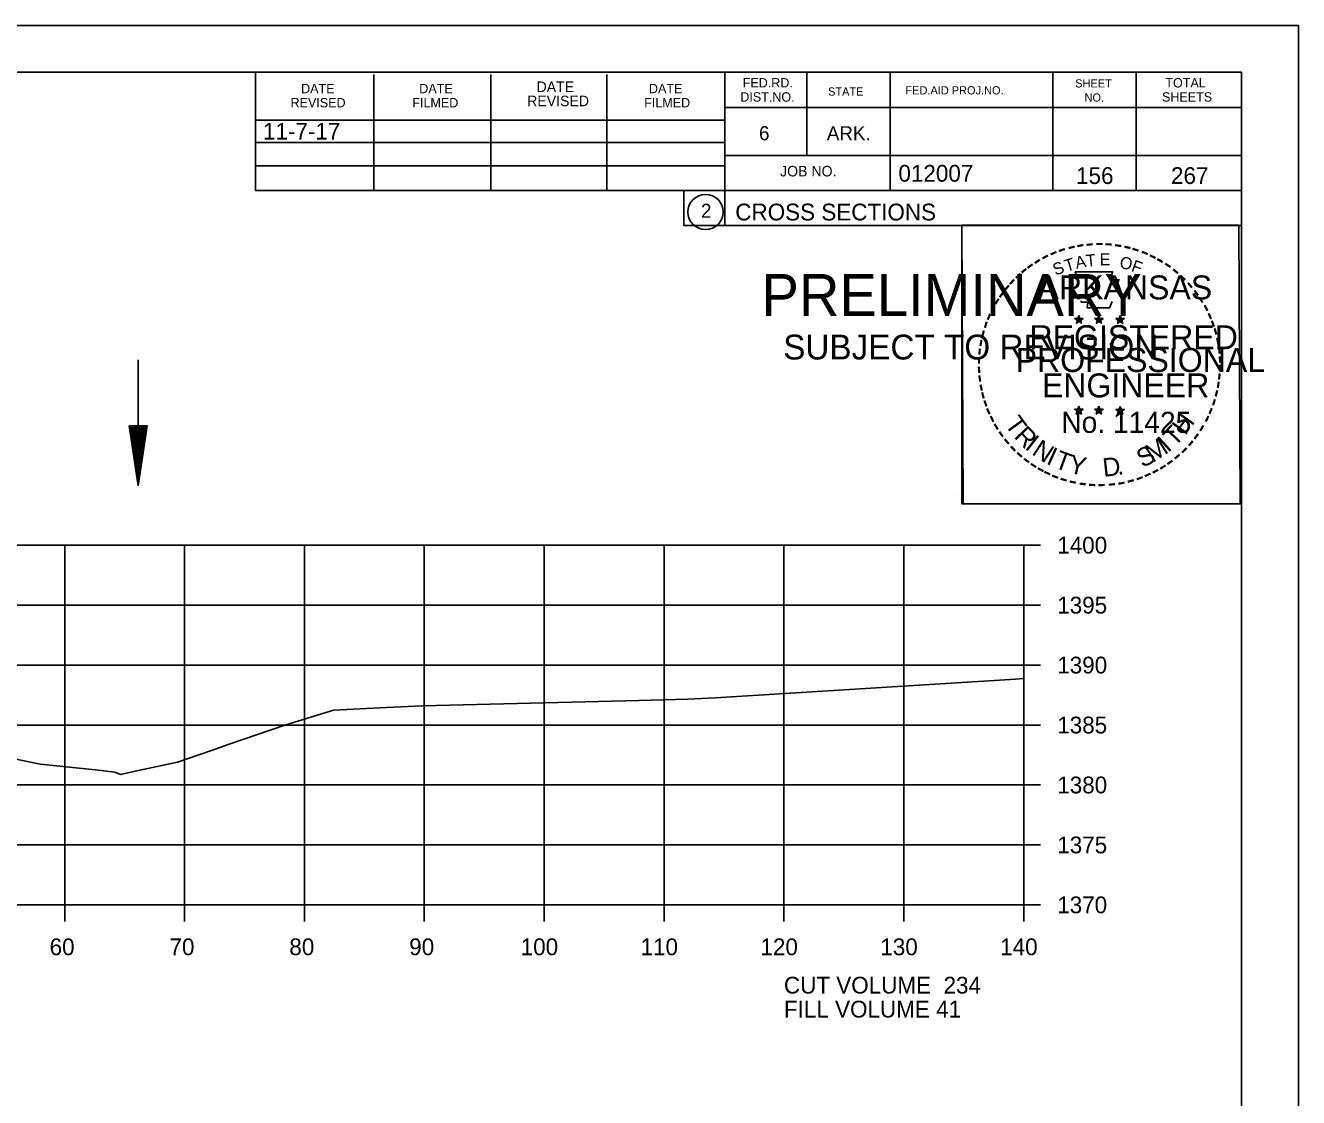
# Model space of a CAD drawing. Extents: x 1374311 to 1383814, y 384102 to 406278.
# Drawn here: x 1381685.4 to 1381791.6, y 385941.9 to 386031.3 of the extents above; entities that cross this region are included whole.
import ezdxf

# ---------------------------------------------------------------- set-up
doc = ezdxf.new("R2010")
doc.units = 0
for name, color, linetype in [('R_Axis', 7, 'Continuous'), ('R_Axis Annot', 7, 'Continuous'), ('R_Border', 7, 'Continuous'), ('R_Border PE', 7, 'Continuous'), ('R_Border Prem', 7, 'Continuous'), ('R_Draft', 7, 'Continuous'), ('R_Exist Surface', 7, 'Continuous'), ('R_Fin Surface', 7, 'Continuous'), ('R_Grid', 7, 'Continuous'), ('R_No Plot', 7, 'Continuous'), ('R_Water', 7, 'Continuous')]:
    doc.layers.add(name, color=color, linetype=linetype)

msp = doc.modelspace()

# ---------------------------------------------------------------- linework, layer by layer
at = {"layer": 'R_Axis'}
for p, q in [((1381768.66, 385957.95), (1381768.66, 385987.95)), ((1381770.06, 385987.95), (1381768.66, 385987.95)), ((1381770.06, 385982.95), (1381768.66, 385982.95)), ((1381770.06, 385977.95), (1381768.66, 385977.95)), ((1381770.06, 385972.95), (1381768.66, 385972.95)), ((1381770.06, 385967.95), (1381768.66, 385967.95)), ((1381770.06, 385962.95), (1381768.66, 385962.95)), ((1381488.66, 385957.95), (1381768.66, 385957.95)), ((1381688.66, 385956.55), (1381688.66, 385957.95)), ((1381698.66, 385956.55), (1381698.66, 385957.95)), ((1381708.66, 385956.55), (1381708.66, 385957.95)), ((1381718.66, 385956.55), (1381718.66, 385957.95)), ((1381728.66, 385956.55), (1381728.66, 385957.95)), ((1381738.66, 385956.55), (1381738.66, 385957.95)), ((1381748.66, 385956.55), (1381748.66, 385957.95)), ((1381758.66, 385956.55), (1381758.66, 385957.95)), ((1381768.66, 385956.55), (1381768.66, 385957.95)), ((1381770.06, 385957.95), (1381768.66, 385957.95))]:
    msp.add_line(p, q, dxfattribs=at)
at = {"layer": 'R_Border'}
for p, q in [((1381470.66, 386027.41), (1381786.84, 386027.41)), ((1381704.58, 386017.53), (1381704.58, 386027.41)), ((1381714.44, 386017.53), (1381714.44, 386027.21)), ((1381724.2, 386017.53), (1381724.2, 386027.21)), ((1381733.88, 386017.53), (1381733.88, 386027.21)), ((1381743.74, 386027.41), (1381743.74, 386014.61)), ((1381750.58, 386027.41), (1381750.58, 386020.47)), ((1381757.52, 386027.41), (1381757.52, 386017.53)), ((1381771.1, 386027.41), (1381771.1, 386017.53)), ((1381778.04, 386027.41), (1381778.04, 386017.53)), ((1381786.84, 385821.95), (1381786.84, 386027.41)), ((1381786.84, 386024.47), (1381743.74, 386024.47)), ((1381786.84, 386024.49), (1381786.84, 386024.49)), ((1381704.58, 386023.39), (1381743.74, 386023.39)), ((1381704.58, 386021.53), (1381743.74, 386021.53)), ((1381786.84, 386020.47), (1381743.74, 386020.47)), ((1381746.7, 386020.47), (1381786.84, 386020.47)), ((1381704.58, 386017.53), (1381704.58, 386019.59)), ((1381704.58, 386019.59), (1381743.74, 386019.59)), ((1381786.84, 386017.53), (1381704.58, 386017.53)), ((1381743.74, 386014.61), (1381786.84, 386014.61))]:
    msp.add_line(p, q, dxfattribs=at)
msp.add_circle((1381742.12, 386015.74), 1.47, dxfattribs=at)
at = {"layer": 'R_Border PE'}
for p, q in [((1381772.92, 386006.86), (1381773.27, 386006.75)), ((1381772.92, 386006.86), (1381773.18, 386006.82)), ((1381772.92, 386006.86), (1381773.16, 386006.74)), ((1381773.06, 386006.46), (1381773.27, 386006.75)), ((1381773.06, 386006.46), (1381773.18, 386006.7)), ((1381773.06, 386006.46), (1381773.27, 386006.67)), ((1381773.27, 386007.12), (1381773.23, 386006.87)), ((1381773.27, 386006.75), (1381773.27, 386007.12)), ((1381773.27, 386007.12), (1381773.32, 386006.87)), ((1381773.62, 386006.86), (1381773.27, 386006.75)), ((1381773.48, 386006.46), (1381773.27, 386006.75)), ((1381773.48, 386006.46), (1381773.27, 386006.67)), ((1381773.62, 386006.86), (1381773.33, 386006.81)), ((1381773.48, 386006.46), (1381773.35, 386006.75)), ((1381773.62, 386006.86), (1381773.41, 386006.76)), ((1381774.59, 386006.86), (1381774.94, 386006.75)), ((1381774.59, 386006.86), (1381774.85, 386006.82)), ((1381774.59, 386006.86), (1381774.83, 386006.74)), ((1381774.73, 386006.46), (1381774.94, 386006.75)), ((1381774.73, 386006.46), (1381774.85, 386006.7)), ((1381774.73, 386006.46), (1381774.94, 386006.67)), ((1381774.94, 386007.12), (1381774.9, 386006.87)), ((1381774.94, 386006.75), (1381774.94, 386007.12)), ((1381774.94, 386007.12), (1381774.99, 386006.87)), ((1381775.29, 386006.86), (1381774.94, 386006.75)), ((1381775.15, 386006.46), (1381774.94, 386006.75)), ((1381775.15, 386006.46), (1381774.94, 386006.67)), ((1381775.29, 386006.86), (1381775, 386006.81)), ((1381775.15, 386006.46), (1381775.02, 386006.75)), ((1381775.29, 386006.86), (1381775.08, 386006.76)), ((1381776.36, 386006.85), (1381776.71, 386006.74)), ((1381776.36, 386006.85), (1381776.61, 386006.81)), ((1381776.36, 386006.85), (1381776.59, 386006.73)), ((1381776.49, 386006.44), (1381776.71, 386006.74)), ((1381776.49, 386006.44), (1381776.62, 386006.69)), ((1381776.49, 386006.44), (1381776.7, 386006.66)), ((1381776.71, 386007.11), (1381776.66, 386006.85)), ((1381776.92, 386006.44), (1381776.7, 386006.66)), ((1381776.71, 386006.74), (1381776.71, 386007.11)), ((1381776.71, 386007.11), (1381776.75, 386006.86)), ((1381777.05, 386006.85), (1381776.71, 386006.74)), ((1381776.92, 386006.44), (1381776.71, 386006.74)), ((1381777.05, 386006.85), (1381776.77, 386006.8)), ((1381776.92, 386006.44), (1381776.78, 386006.73)), ((1381777.05, 386006.85), (1381776.85, 386006.75)), ((1381772.92, 385999.29), (1381773.27, 385999.18)), ((1381772.92, 385999.29), (1381773.17, 385999.25)), ((1381772.92, 385999.29), (1381773.16, 385999.17)), ((1381773.05, 385998.88), (1381773.27, 385999.18)), ((1381773.05, 385998.88), (1381773.18, 385999.13)), ((1381773.05, 385998.88), (1381773.27, 385999.1)), ((1381773.27, 385999.54), (1381773.23, 385999.29)), ((1381773.27, 385999.18), (1381773.27, 385999.54)), ((1381773.27, 385999.54), (1381773.32, 385999.29)), ((1381773.61, 385999.29), (1381773.27, 385999.18)), ((1381773.48, 385998.88), (1381773.27, 385999.18)), ((1381773.48, 385998.88), (1381773.27, 385999.1)), ((1381773.61, 385999.29), (1381773.33, 385999.24)), ((1381773.48, 385998.88), (1381773.34, 385999.17)), ((1381773.61, 385999.29), (1381773.41, 385999.19)), ((1381774.59, 385999.29), (1381774.94, 385999.18)), ((1381774.59, 385999.29), (1381774.84, 385999.25)), ((1381774.59, 385999.29), (1381774.82, 385999.17)), ((1381774.72, 385998.88), (1381774.94, 385999.18)), ((1381774.72, 385998.88), (1381774.85, 385999.13)), ((1381774.72, 385998.88), (1381774.93, 385999.1)), ((1381774.94, 385999.54), (1381774.9, 385999.29)), ((1381775.15, 385998.88), (1381774.93, 385999.1)), ((1381774.94, 385999.18), (1381774.94, 385999.54)), ((1381774.94, 385999.54), (1381774.99, 385999.29)), ((1381775.28, 385999.29), (1381774.94, 385999.18)), ((1381775.15, 385998.88), (1381774.94, 385999.18)), ((1381775.28, 385999.29), (1381775, 385999.24)), ((1381775.15, 385998.88), (1381775.01, 385999.17)), ((1381775.28, 385999.29), (1381775.08, 385999.19)), ((1381776.35, 385999.28), (1381776.7, 385999.17)), ((1381776.35, 385999.28), (1381776.61, 385999.24)), ((1381776.35, 385999.28), (1381776.59, 385999.16)), ((1381776.49, 385998.87), (1381776.7, 385999.17)), ((1381776.49, 385998.87), (1381776.61, 385999.12)), ((1381776.49, 385998.87), (1381776.7, 385999.09)), ((1381776.7, 385999.53), (1381776.66, 385999.28)), ((1381776.7, 385999.17), (1381776.7, 385999.53)), ((1381776.7, 385999.53), (1381776.75, 385999.28)), ((1381777.05, 385999.28), (1381776.7, 385999.17)), ((1381776.92, 385998.87), (1381776.7, 385999.17)), ((1381776.92, 385998.87), (1381776.7, 385999.09)), ((1381777.05, 385999.28), (1381776.76, 385999.23)), ((1381776.92, 385998.87), (1381776.78, 385999.16)), ((1381777.05, 385999.28), (1381776.85, 385999.18))]:
    msp.add_line(p, q, dxfattribs=at)
for points in [[(1381772.96, 386010.74), (1381773.23, 386009.91)], [(1381776.47, 386009.82), (1381776.62, 386010.1), (1381775.93, 386010.08), (1381776.08, 386010.74), (1381772.96, 386010.74)], [(1381773.46, 386008.32), (1381773.46, 386008.23), (1381774.02, 386008.21), (1381773.96, 386007.74), (1381775.83, 386007.74), (1381776.04, 386008.28)], [(1381773.27, 386007.12), (1381773.48, 386006.46), (1381772.92, 386006.86), (1381773.62, 386006.86), (1381773.06, 386006.46), (1381773.27, 386007.12)], [(1381774.94, 386007.12), (1381775.15, 386006.46), (1381774.59, 386006.86), (1381775.29, 386006.86), (1381774.73, 386006.46), (1381774.94, 386007.12)], [(1381776.71, 386007.11), (1381776.92, 386006.44), (1381776.36, 386006.85), (1381777.05, 386006.85), (1381776.49, 386006.44), (1381776.71, 386007.11)], [(1381773.27, 385999.54), (1381773.48, 385998.88), (1381772.92, 385999.29), (1381773.61, 385999.29), (1381773.05, 385998.88), (1381773.27, 385999.54)], [(1381774.94, 385999.54), (1381775.15, 385998.88), (1381774.59, 385999.29), (1381775.28, 385999.29), (1381774.72, 385998.88), (1381774.94, 385999.54)], [(1381776.7, 385999.53), (1381776.92, 385998.87), (1381776.35, 385999.28), (1381777.05, 385999.28), (1381776.49, 385998.87), (1381776.7, 385999.53)]]:
    msp.add_lwpolyline(points, dxfattribs=at)
for centre, radius in [((1381773.27, 386006.75), 0.172), ((1381773.27, 386006.75), 0.145), ((1381773.27, 386006.75), 0.116), ((1381773.27, 386006.75), 0.0991), ((1381773.27, 386006.75), 0.0747), ((1381773.27, 386006.75), 0.0495), ((1381773.27, 386006.75), 0.0296), ((1381774.94, 386006.75), 0.172), ((1381774.94, 386006.75), 0.145), ((1381774.94, 386006.75), 0.116), ((1381774.94, 386006.75), 0.0991), ((1381774.94, 386006.75), 0.0747), ((1381774.94, 386006.75), 0.0495), ((1381774.94, 386006.75), 0.0296), ((1381776.7, 386006.74), 0.172), ((1381776.7, 386006.74), 0.145), ((1381776.7, 386006.74), 0.116), ((1381776.7, 386006.74), 0.0991), ((1381776.7, 386006.74), 0.0747), ((1381776.7, 386006.74), 0.0495), ((1381776.7, 386006.74), 0.0296), ((1381773.27, 385999.18), 0.172), ((1381773.27, 385999.18), 0.145), ((1381773.27, 385999.18), 0.116), ((1381773.27, 385999.18), 0.0991), ((1381773.27, 385999.18), 0.0747), ((1381773.27, 385999.18), 0.0495), ((1381773.27, 385999.18), 0.0296), ((1381774.94, 385999.18), 0.172), ((1381774.94, 385999.18), 0.145), ((1381774.94, 385999.18), 0.116), ((1381774.94, 385999.18), 0.0991), ((1381774.94, 385999.18), 0.0747), ((1381774.94, 385999.18), 0.0495), ((1381774.94, 385999.18), 0.0296), ((1381776.7, 385999.17), 0.172), ((1381776.7, 385999.17), 0.145), ((1381776.7, 385999.17), 0.116), ((1381776.7, 385999.17), 0.0991), ((1381776.7, 385999.17), 0.0747), ((1381776.7, 385999.17), 0.0495), ((1381776.7, 385999.17), 0.0296)]:
    msp.add_circle(centre, radius, dxfattribs=at)
at = {"layer": 'R_Draft'}
for p, q in [((1381694.03, 385997.9), (1381694.78, 385992.9)), ((1381695.53, 385997.9), (1381694.03, 385997.9)), ((1381694.15, 385997.9), (1381694.78, 385993.74)), ((1381694.28, 385997.9), (1381694.78, 385994.6)), ((1381694.41, 385997.9), (1381694.78, 385995.43)), ((1381694.53, 385997.9), (1381694.78, 385996.28)), ((1381694.66, 385997.9), (1381694.78, 385997.11)), ((1381695.53, 385997.9), (1381694.78, 385992.9)), ((1381695.02, 385997.9), (1381694.78, 385996.28)), ((1381695.28, 385997.9), (1381694.78, 385994.6)), ((1381695.4, 385997.9), (1381694.78, 385993.74)), ((1381695.15, 385997.9), (1381694.78, 385995.43)), ((1381694.9, 385997.9), (1381694.78, 385997.11))]:
    msp.add_line(p, q, dxfattribs=at)
at = {"layer": 'R_Exist Surface'}
msp.add_lwpolyline([(1381684.47, 385970.14), (1381686.6, 385969.69), (1381691.22, 385969.22), (1381692.83, 385969.02), (1381693.31, 385968.83), (1381694.68, 385969.13), (1381698.08, 385969.85), (1381700.91, 385970.82), (1381702.37, 385971.34), (1381707.02, 385972.95), (1381711.08, 385974.2), (1381715.51, 385974.41), (1381718.52, 385974.56), (1381736.59, 385975), (1381740.62, 385975.1), (1381742.95, 385975.21), (1381767.99, 385976.77), (1381768.66, 385976.82)], dxfattribs=at)
at = {"layer": 'R_Grid'}
for p, q in [((1381488.66, 385987.95), (1381768.66, 385987.95)), ((1381688.66, 385957.95), (1381688.66, 385987.95)), ((1381698.66, 385957.95), (1381698.66, 385987.95)), ((1381708.66, 385957.95), (1381708.66, 385987.95)), ((1381718.66, 385957.95), (1381718.66, 385987.95)), ((1381728.66, 385957.95), (1381728.66, 385987.95)), ((1381738.66, 385957.95), (1381738.66, 385987.95)), ((1381748.66, 385957.95), (1381748.66, 385987.95)), ((1381758.66, 385957.95), (1381758.66, 385987.95)), ((1381768.66, 385957.95), (1381768.66, 385987.95)), ((1381488.66, 385982.95), (1381768.66, 385982.95)), ((1381488.66, 385977.95), (1381768.66, 385977.95)), ((1381488.66, 385972.95), (1381768.66, 385972.95)), ((1381488.66, 385967.95), (1381768.66, 385967.95)), ((1381488.66, 385962.95), (1381768.66, 385962.95)), ((1381488.66, 385957.95), (1381768.66, 385957.95))]:
    msp.add_line(p, q, dxfattribs=at)
at = {"layer": 'R_No Plot'}
for p, q in [((1381458.26, 386031.3), (1381791.59, 386031.3)), ((1381762.87, 385992.15), (1381762.87, 385992.15))]:
    msp.add_line(p, q, dxfattribs=at)
for points in [[(1381458.25, 386031.3), (1381791.59, 386031.3), (1381791.59, 385817.97), (1381458.25, 385817.97)], [(1381704.58, 386027.41), (1381704.58, 386017.53), (1381740.31, 386017.53), (1381740.31, 386014.61), (1381763.51, 386014.61), (1381763.51, 385991.39), (1381786.84, 385991.39), (1381786.84, 385821.95), (1381470.66, 385821.95), (1381470.66, 386027.41)], [(1381763.51, 386014.64), (1381786.61, 386014.64), (1381786.72, 385991.39), (1381763.62, 385991.39)]]:
    msp.add_lwpolyline(points, close=True, dxfattribs=at)
at = {"layer": 'R_Water'}
msp.add_line((1381694.78, 386003.41), (1381694.78, 385992.9), dxfattribs=at)

# ---------------------------------------------------------------- texts
at = {"layer": 'R_Axis Annot'}
for s, p in [('1400', (1381771.46, 385987.25)), ('1395', (1381771.46, 385982.25)), ('1390', (1381771.46, 385977.25)), ('1385', (1381771.46, 385972.25)), ('1380', (1381771.46, 385967.25)), ('1375', (1381771.46, 385962.25)), ('1370', (1381771.46, 385957.25)), ('60', (1381687.4, 385953.75)), ('70', (1381697.4, 385953.75)), ('80', (1381707.4, 385953.75)), ('90', (1381717.4, 385953.75)), ('100', (1381726.7, 385953.75)), ('110', (1381736.7, 385953.75)), ('120', (1381746.7, 385953.75)), ('130', (1381756.7, 385953.75)), ('140', (1381766.7, 385953.75)), ('CUT VOLUME  234', (1381748.66, 385950.55)), ('FILL VOLUME 41', (1381748.66, 385948.55))]:
    msp.add_text(s, height=1.4, dxfattribs=at).set_placement(p)
at = {"layer": 'R_Border'}
for s, height, p in [('DATE', 0.879, (1381728.02, 386025.75)), ('FED.RD.', 0.782, (1381745.22, 386026.13)), ('SHEET', 0.684, (1381772.96, 386026.13)), ('TOTAL', 0.782, (1381780.48, 386026.13)), ('DATE', 0.782, (1381708.38, 386025.65)), ('DATE', 0.782, (1381718.24, 386025.65)), ('DATE', 0.782, (1381737.4, 386025.65)), ('DIST.NO.', 0.782, (1381745.02, 386024.95)), ('STATE', 0.684, (1381752.34, 386025.45)), ('FED.AID PROJ.NO.', 0.684, (1381758.8, 386025.55)), ('NO.', 0.684, (1381773.74, 386024.95)), ('SHEETS', 0.782, (1381780.2, 386024.95)), ('REVISED', 0.782, (1381707.5, 386024.47)), ('FILMED', 0.782, (1381717.66, 386024.47)), ('REVISED', 0.879, (1381727.24, 386024.57)), ('FILMED', 0.782, (1381737, 386024.47)), ('6', 1.17, (1381746.58, 386021.73)), ('ARK.', 1.172, (1381752.24, 386021.73)), ('JOB NO.', 0.879, (1381748.34, 386018.71)), ('012007', 1.4, (1381758.21, 386018.27)), ('2', 1.17, (1381741.74, 386015.26)), ('CROSS SECTIONS', 1.4, (1381744.6, 386015.04))]:
    msp.add_text(s, height=height, rotation=360, dxfattribs=at).set_placement(p)
at = {"layer": 'R_Border PE'}
for s, height, rotation, p in [('-', 1.6, 13.6301, (1381772.46, 386012.11)), ('-', 1.6, 10.2193, (1381773.14, 386012.27)), ('-', 1.6, 5.8968, (1381773.87, 386012.38)), ('-', 1.6, 0.1862, (1381774.64, 386012.45)), ('-', 1.6, 357.743, (1381775.36, 386012.44)), ('-', 1.6, 352.1617, (1381776.11, 386012.38)), ('-', 1.6, 347.2049, (1381776.83, 386012.27)), ('-', 1.6, 34.0636, (1381769.85, 386010.91)), ('-', 1.6, 28.7918, (1381770.44, 386011.28)), ('-', 1.6, 24.3072, (1381771.08, 386011.6)), ('-', 1.6, 19.1761, (1381771.71, 386011.87)), ('T', 1, 16.4036, (1381772.23, 386010.75)), ('A', 1, 11.2132, (1381773.06, 386011)), ('T', 1, 6.0228, (1381773.91, 386011.17)), ('E', 1, 0.8323, (1381775.01, 386011.28)), ('O', 1, 350.4515, (1381776.62, 386011.07)), ('F', 1, 340.0707, (1381777.57, 386010.84)), ('-', 1.6, 342.3362, (1381777.46, 386012.12)), ('-', 1.6, 337.8551, (1381778.2, 386011.89)), ('-', 1.6, 334.1211, (1381778.83, 386011.62)), ('-', 1.6, 329.6409, (1381779.41, 386011.34)), ('-', 1.6, 42.9622, (1381768.36, 386009.72)), ('-', 1.6, 38.9507, (1381768.79, 386010.14)), ('-', 1.6, 36.2317, (1381769.27, 386010.52)), ('S', 1, 21.594, (1381771.32, 386010.42)), ('-', 1.6, 325.8627, (1381780.05, 386010.98)), ('-', 1.6, 320.5297, (1381780.66, 386010.55)), ('-', 1.6, 50.6142, (1381767.51, 386008.76)), ('-', 1.6, 48.423, (1381767.91, 386009.24)), ('ARKANSAS', 2, 360, (1381769.82, 386008.45)), ('-', 1.6, 315.5786, (1381781.26, 386010.06)), ('-', 1.6, 309.8797, (1381781.83, 386009.51)), ('-', 1.6, 58.0706, (1381766.77, 386007.66)), ('-', 1.6, 54.2325, (1381767.1, 386008.19)), ('-', 1.6, 306.6522, (1381782.35, 386008.91)), ('-', 1.4, 303.6753, (1381782.84, 386008.34)), ('-', 1.6, 62.8713, (1381766.46, 386007.05)), ('-', 1.6, 299.6684, (1381783.16, 386007.74)), ('-', 1.6, 72.3945, (1381765.98, 386005.81)), ('-', 1.6, 67.7743, (1381766.2, 386006.44)), ('DWB', 0.01, 360, (1381773.26, 386006.75)), ('DWB', 0.01, 360, (1381774.93, 386006.75)), ('DWB', 0.01, 360, (1381776.69, 386006.74)), ('-', 1.6, 294.6628, (1381783.48, 386007.12)), ('-', 1.6, 290.5728, (1381783.74, 386006.55)), ('-', 1.6, 75.461, (1381765.78, 386005.1)), ('REGISTERED', 2, 360, (1381769.14, 386004.3)), ('-', 1.6, 285.1233, (1381783.97, 386005.97)), ('-', 1.6, 85.1863, (1381765.57, 386003.69)), ('-', 1.6, 81.2013, (1381765.65, 386004.38)), ('PROFESSIONAL', 2, 360, (1381767.99, 386002.4)), ('-', 1.6, 280.5493, (1381784.17, 386005.23)), ('-', 1.6, 276.5962, (1381784.33, 386004.46)), ('-', 1.6, 89.0622, (1381765.55, 386002.99)), ('-', 1.6, 274.3301, (1381784.39, 386003.74)), ('-', 1.6, 94.1959, (1381765.58, 386002.27)), ('ENGINEER', 2, 360, (1381770.18, 386000.28)), ('-', 1.6, 263.5172, (1381784.41, 386002.44)), ('-', 1.6, 269.9407, (1381784.43, 386003.1)), ('-', 1.6, 98.9479, (1381765.66, 386001.6)), ('-', 1.6, 101.7149, (1381765.79, 386000.87)), ('-', 1.6, 260.9953, (1381784.34, 386001.78)), ('-', 1.6, 105.4578, (1381765.95, 386000.27)), ('-', 1.6, 109.0874, (1381766.17, 385999.64)), ('-', 1.6, 252.8681, (1381784.05, 386000.39)), ('-', 1.6, 255.7626, (1381784.23, 386001.11)), ('-', 1.6, 114.0643, (1381766.42, 385999.04)), ('No. 11425', 1.757, 360, (1381771.8, 385997.32)), ('DWB', 0.01, 360, (1381773.25, 385999.17)), ('DWB', 0.01, 360, (1381774.92, 385999.17)), ('DWB', 0.01, 360, (1381776.69, 385999.16)), ('H', 1.54, 54.6088, (1381782.15, 385997.05)), ('-', 1.6, 247.8887, (1381783.82, 385999.71)), ('-', 1.6, 115.7289, (1381766.73, 385998.43)), ('-', 1.6, 120.4471, (1381767.08, 385997.84)), ('T', 1.54, 306.0406, (1381767.03, 385998.02)), ('R', 1.54, 314.005, (1381767.79, 385996.97)), ('T', 1.54, 46.6444, (1381781.26, 385996.11)), ('-', 1.6, 239.0712, (1381783.17, 385998.33)), ('-', 1.6, 244.6197, (1381783.56, 385999.08)), ('-', 1.6, 125.8934, (1381767.49, 385997.28)), ('I', 1.54, 321.9694, (1381768.69, 385996.04)), ('M', 1.54, 32.6563, (1381779.41, 385994.79)), ('I', 1.54, 42.1136, (1381780.7, 385995.63)), ('-', 1.6, 233.8452, (1381782.77, 385997.68)), ('-', 1.6, 130.7181, (1381767.95, 385996.73)), ('-', 1.6, 134.2238, (1381768.47, 385996.18)), ('N', 1.54, 326.5002, (1381769.26, 385995.57)), ('I', 1.54, 335.3603, (1381770.47, 385994.78)), ('T', 1.54, 339.8912, (1381771.13, 385994.45)), ('S', 1.54, 26.9312, (1381778.57, 385994.38)), ('-', 1.6, 225.7653, (1381781.86, 385996.55)), ('-', 1.6, 231.2538, (1381782.34, 385997.11)), ('-', 1.6, 138.9338, (1381768.99, 385995.72)), ('-', 1.6, 144.6463, (1381769.55, 385995.31)), ('-', 1.6, 148.0898, (1381770.11, 385994.94)), ('Y', 1.54, 347.8556, (1381772.34, 385994.01)), ('D', 1.54, 6.3969, (1381775.33, 385993.65)), ('-', 1.6, 215.7363, (1381780.79, 385995.57)), ('-', 1.6, 221.0851, (1381781.33, 385996.04)), ('-', 1.6, 151.5704, (1381770.69, 385994.62)), ('-', 1.6, 154.6002, (1381771.21, 385994.37)), ('-', 1.6, 158.5612, (1381771.83, 385994.11)), ('.', 1.54, 13.7642, (1381776.52, 385993.78)), ('-', 1.6, 200.7184, (1381778.45, 385994.24)), ('-', 1.6, 204.2516, (1381779.07, 385994.52)), ('-', 1.6, 207.3568, (1381779.69, 385994.83)), ('-', 1.6, 212.2491, (1381780.25, 385995.18)), ('-', 1.6, 162.7983, (1381772.52, 385993.9)), ('-', 1.6, 167.5555, (1381773.24, 385993.74)), ('-', 1.6, 173.1155, (1381774.01, 385993.63)), ('-', 1.6, 176.5183, (1381774.76, 385993.57)), ('-', 1.6, 181.5918, (1381775.5, 385993.59)), ('-', 1.6, 185.8167, (1381776.31, 385993.67)), ('-', 1.6, 191.2858, (1381777.04, 385993.8)), ('-', 1.6, 195.4743, (1381777.77, 385994))]:
    msp.add_text(s, height=height, rotation=rotation, dxfattribs=at).set_placement(p)
at = {"layer": 'R_Border Prem'}
for s, height, p in [('PRELIMINARY', 3.5, (1381746.79, 386007.07)), ('DWB', 0.01, (1381747.53, 386008.92)), ('SUBJECT TO REVISION', 2.0751, (1381748.6, 386003.44))]:
    msp.add_text(s, height=height, rotation=360, dxfattribs=at).set_placement(p)
at = {"layer": 'R_Fin Surface'}
msp.add_text('11-7-17', height=1.4, dxfattribs=at).set_placement((1381705.2, 386021.78))
at = {"layer": 'R_Water'}
for s, p in [('156', (1381773.03, 386018.08)), ('267', (1381780.95, 386018.08))]:
    msp.add_text(s, height=1.4, rotation=360, dxfattribs=at).set_placement(p)

doc.saveas('drawing.dxf')
